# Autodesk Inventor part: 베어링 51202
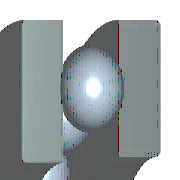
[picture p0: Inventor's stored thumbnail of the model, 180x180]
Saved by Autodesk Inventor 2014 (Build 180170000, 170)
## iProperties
Created: 2012-02
Part Number: 베어링 51202
Material: 강철, 연강
Description: 롤링 베어링 - 플랫 뒷면이 있는 스러스트 볼 베어링
Document SubType Name: Modeling
Standard: KS B 2022
Designer: mduedu
Standards Organization: KS
Language: ko-KR
Size Designation: 51202 - 15 x 32 x 12
Categories: <MemberInstance><Categories><Category DisplayName="샤프트 부품" InternalName="7f7aeb1f-a693-4053-b835-cee3144e0d98" Mnemonic="SHFT"><Category DisplayName="베어링" Inter
Density: 1 g/cm^3
Appearance: 진녹색
IsCustomPart: 1
Author: mduedu
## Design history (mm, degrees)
sketch "스케치1" dims "d3" = 5.28 (= 0.44 x KB)
  geometry: L1 (6, 9.61)-(6, 14.89); L2 (8.64, 12.25)-(3.36, 12.25); L3 (3.6, 16)-(0, 16); L4 (3.6, 7.5)-(0, 7.5); L5 (8.4, 13.35)-(8.4, 16); L6 (8.4, 16)-(12, 16); L7 (12, 16)-(12, 8.5); L8 (12, 8.5)-(8.4, 8.5); L9 (8.4, 8.5)-(8.4, 11.15); L10 (3.6, 16)-(3.6, 13.35); L11 (3.6, 11.15)-(3.6, 7.5); L12 (-1.8, 0)-(10.8, 0) reference; L13 (0, -0.022)-(0, 5.522) reference; 1 further point
  constraints: 22 end point, 5 perpendicular, 2 equal length, 2 midpoint, 2 parallel, 2 point on line, 1 collinear, 10 other
  dimensions: "d8" = 4.8 diameter of L11 L1 (= 0.4 x KB); "d11" = 15 diameter of L4 L12 (= WD); "d12" = 17 diameter of L8 L12 (= KAD1); "d13" = 32 diameter of L3 L12 (= KID1); "d14" = 32 diameter of L6 L12 (= BD); "d15" = 24.5 diameter of point (6, 12.25) L12 (= 0.5 x KID1 + 0.5 x KAD1); "d16" = 6 distance from line of point (6, 12.25) L13 (= 0.5 x KB); "d18" = 12 distance between parallel lines of L7 L13 (= KB)
revolve "본체" stored, may be unused: angle "d9" = 90 deg
revolve "볼" stored, may be unused: angle "d10" = 90 deg
pattern_circular "IDS_ARRAYBALL[SIMPL:T]" dims angle "d2" = 360 deg
body "Solid1"
fillet "모깎기1" dims "d4" = 0.6 (= KRS)
fillet "모깎기2" dims "d5" = 0.6 (= KRS)
other parameters: "WD" = 15 [user parameter; used in 2 equation terms], "KAD1" = 17 [user parameter; used in 3 equation terms], "KID1" = 32 [user parameter; used in 3 equation terms], "BD" = 32 [user parameter; used in 2 equation terms], "KB" = 12 [user parameter; used in 6 equation terms], "KRS" = 0.6 [user parameter; used in 2 equation terms], "d0" = 2.4 (= 0.2 x KB), "d6" = 0, "d7" = 0, "d19" = 0, "d41" = 0, "d42" = 0, "WR" = 7.5 (= 0.5 x WD) [user parameter], "BC" = 1.65e+07 [user parameter], "BBA" = 90 deg [user parameter], "BC0" = 2.7e+07 [user parameter], "BR" = 16 (= 0.5 x BD) [user parameter]
